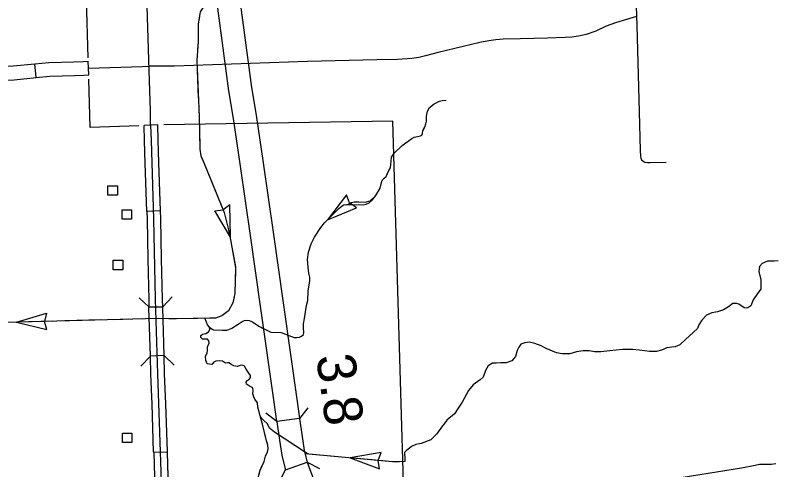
# Model space of a CAD drawing. Extents: x 155 to 3386, y 68 to 2138.
# Drawn here: x 1365.4 to 1602.6, y 911.3 to 1053.4 of the extents above; entities that cross this region are included whole.
import ezdxf

# ---------------------------------------------------------------- set-up
doc = ezdxf.new("R2010")
doc.units = 0
for name, color, linetype in [('Level 10', 7, 'Continuous'), ('Level 31', 7, 'Continuous'), ('Level 32', 7, 'Continuous'), ('Level 33', 7, 'Continuous'), ('Level 34', 7, 'Continuous'), ('Level 35', 7, 'Continuous'), ('Level 37', 7, 'Continuous'), ('Level 38', 7, 'Continuous'), ('Level 43', 7, 'Continuous'), ('Level 48', 7, 'Continuous'), ('Level 56', 7, 'Continuous'), ('Level 6', 7, 'Continuous')]:
    doc.layers.add(name, color=color, linetype=linetype)

msp = doc.modelspace()

# ---------------------------------------------------------------- linework, layer by layer
at = {"layer": 'Level 10'}
for p, q in [((1454.12, 927.28), (1447.04, 926.37)), ((1449.83, 911.26), (1456.56, 913.66))]:
    msp.add_line(p, q, dxfattribs=at)
for points in [[(1435.56, 1058.02), (1436.15, 1053.35), (1439.21, 1030.75), (1440.63, 1022.15), (1442.82, 1007.23), (1445.93, 985.55), (1449.17, 962.7), (1453.34, 933.37), (1454.12, 927.28)], [(1447.04, 926.37), (1446.26, 932.41), (1442.1, 961.7), (1438.86, 984.54), (1435.75, 1006.2), (1433.57, 1021.05), (1432.14, 1029.69), (1429.07, 1052.42), (1428.47, 1057.12)], [(1447.04, 926.37), (1447.06, 926.21), (1447.91, 920.57), (1448.64, 915.88), (1449.56, 912.02), (1449.83, 911.26)], [(1454.12, 927.28), (1454.13, 927.2), (1454.97, 921.66), (1455.66, 917.26), (1456.42, 914.06), (1456.56, 913.66)], [(1456.56, 913.66), (1457.39, 911.35), (1458.43, 908.69), (1459.74, 906.21), (1461.44, 903.5), (1463.17, 901.07), (1465.56, 898.29), (1467.5, 896.43), (1469.83, 894.48), (1472.23, 892.84), (1475.97, 890.67), (1486.91, 884.81)]]:
    msp.add_lwpolyline(points, dxfattribs=at)
at = {"layer": 'Level 31'}
for p, q in [((1410.78, 992.2), (1406.5, 992.05)), ((1410.78, 992.2), (1410.78, 992.2)), ((1407.21, 962.16), (1411.49, 962.24)), ((1411.89, 946.95), (1407.61, 946.82)), ((1412.91, 916.8), (1408.63, 916.66))]:
    msp.add_line(p, q, dxfattribs=at)
for points in [[(1410.28, 1007.27), (1410.05, 1014.28), (1409.9, 1019.04), (1405.62, 1018.9)], [(1406, 1007.13), (1405.77, 1014.14), (1405.62, 1018.9)], [(1420.96, 585), (1420.5, 602.36), (1419.65, 626.77), (1419.02, 651.18), (1418.35, 675.21), (1417.43, 699.69), (1416.62, 724.28), (1415.88, 748.76), (1415.17, 772.25), (1414.5, 794.97), (1413.66, 819.52), (1412.85, 843.76), (1412.35, 867.99), (1411.58, 891.84), (1410.77, 916.92), (1409.92, 941.23), (1409.21, 964.58), (1408.72, 989.66), (1407.91, 1014.21), (1407.76, 1018.97)], [(1406.5, 992.05), (1406, 1007.13)], [(1410.78, 992.2), (1410.28, 1007.27)], [(1406.5, 992.05), (1406.58, 989.61), (1406.83, 977)], [(1411.11, 977.09), (1410.86, 989.72), (1410.78, 992.2)], [(1406.83, 977), (1407.07, 964.53), (1407.15, 961.9)], [(1411.44, 962.03), (1411.36, 964.63), (1411.11, 977.09)], [(1407.61, 946.82), (1407.15, 961.9)], [(1411.89, 946.95), (1411.44, 962.03)], [(1408.11, 931.73), (1407.78, 941.16), (1407.61, 946.82)], [(1412.39, 931.88), (1412.06, 941.3), (1411.89, 946.95)], [(1408.63, 916.66), (1408.62, 916.85), (1408.11, 931.73)], [(1412.91, 916.8), (1412.91, 916.99), (1412.39, 931.88)], [(1408.63, 916.66), (1409.12, 901.58)], [(1413.4, 901.72), (1412.91, 916.8)]]:
    msp.add_lwpolyline(points, dxfattribs=at)
at = {"layer": 'Level 32'}
msp.add_line((1371.94, 1033.86), (1371.53, 1038.13), dxfattribs=at)
for points in [[(1356.6, 1037.18), (1364.8, 1037.48), (1371.53, 1038.13)], [(1371.53, 1038.13), (1375.88, 1038.55), (1383.72, 1038.83), (1386.72, 1038.92)], [(1386.72, 1038.92), (1388.21, 1038.97)], [(1386.86, 1034.64), (1388.35, 1034.68), (1388.21, 1038.97)], [(1371.94, 1033.86), (1376.16, 1034.27), (1383.86, 1034.54), (1386.86, 1034.64)], [(1356.76, 1032.9), (1365.08, 1033.2), (1371.94, 1033.86)]]:
    msp.add_lwpolyline(points, dxfattribs=at)
at = {"layer": 'Level 33'}
for points in [[(1564.93, 1075.72), (1560.18, 1074.28), (1559.67, 1073.92), (1559.16, 1073.37), (1558.88, 1072.82), (1558.8, 1072.11), (1558.8, 1071.16), (1559.51, 1050.17), (1560.22, 1023.19), (1560.5, 1011.04), (1560.62, 1009.27), (1560.73, 1008.72), (1561.01, 1008.2), (1561.44, 1007.77), (1562.04, 1007.45), (1562.82, 1007.3), (1563.65, 1007.3), (1568.66, 1007.42)], [(1407.66, 1018.97), (1407.61, 1023.44), (1407.2, 1036.12), (1406.36, 1062.97)], [(1559.42, 1052.99), (1556.25, 1052.01), (1552.82, 1050.94), (1549.91, 1049.88), (1546.67, 1048.38), (1543.72, 1047.31), (1541.31, 1046.8), (1539.22, 1046.49), (1537.17, 1046.37), (1531.61, 1046.17), (1523.06, 1045.93), (1517.77, 1045.82), (1515.53, 1045.62), (1513.32, 1045.38), (1510.52, 1044.83), (1497.51, 1041.67), (1493.49, 1040.61), (1491.48, 1040.18), (1489.23, 1039.86), (1484.81, 1039.5), (1478.29, 1039.43), (1456.65, 1038.91), (1415.13, 1037.45), (1407.16, 1037.44)]]:
    msp.add_lwpolyline(points, dxfattribs=at)
at = {"layer": 'Level 34'}
msp.add_lwpolyline([(1388.28, 1036.83), (1405.08, 1037.35), (1407.16, 1037.44)], dxfattribs=at)
at = {"layer": 'Level 35'}
for points in [[(1493.29, 1018.35), (1493.65, 1019.43), (1493.81, 1020.24), (1493.81, 1021.78), (1494.14, 1023.39), (1494.78, 1024.48), (1496.27, 1025.61), (1497.85, 1026.5), (1498.7, 1026.74), (1499.99, 1026.82)], [(1603.68, 976.54), (1602.36, 976.44), (1601.34, 976.44), (1600.27, 976.44), (1598.6, 975.73), (1597.78, 974.86), (1597.58, 973.29), (1598.19, 970.69), (1598.19, 969.37), (1598.19, 967.69), (1597.22, 966.32), (1595.8, 964.39), (1595.09, 962.49), (1594.22, 961.88), (1593.66, 961.83), (1593, 961.88), (1591.38, 963.05), (1590.67, 963.26), (1589.45, 963.2), (1588.12, 962.19), (1586.6, 961.27), (1584.72, 960.61), (1582.89, 960.36), (1581.26, 959.65), (1579.84, 958.07), (1578.88, 956.54), (1578.47, 955.42), (1577.15, 954.2), (1574.66, 951.97), (1572.93, 950.29), (1571.51, 949.73), (1570.44, 949.58), (1568.91, 949.42), (1567.24, 948.66), (1565.61, 948.26), (1564.44, 948.26), (1563.42, 948.26), (1560.32, 948.71), (1558.14, 948.87), (1555.04, 948.87), (1551.07, 948.46), (1548.22, 948.1), (1546.34, 948.1), (1544.66, 948.41), (1542.78, 948.41), (1540.65, 948.1), (1538.62, 947.54), (1536.18, 947.49), (1534.45, 947.8), (1531.2, 949.22), (1529.62, 950.03), (1527.64, 950.75), (1526.01, 951.15), (1524.49, 950.95), (1523.32, 950.49), (1522.71, 949.58), (1522.15, 948.51), (1521.64, 946.68), (1520.47, 945.31), (1518.74, 944.7), (1517.07, 944.7), (1515.7, 944.59), (1514.48, 944.59), (1513.05, 943.78), (1512.29, 942.26), (1511.53, 940.27), (1510.56, 939.41), (1508.38, 937.78), (1506.9, 936), (1504.97, 932.44), (1503.9, 930.81), (1502.53, 928.73), (1500.19, 926.8), (1499.08, 925.22), (1498.82, 925.02), (1496.94, 922.42), (1495.21, 920.64), (1492.21, 919.47), (1490.54, 919.22), (1489.11, 918.56), (1487.49, 917.24)], [(1441.11, 930.84), (1441.06, 932.16), (1440.19, 933.39), (1439.89, 934.1), (1439.64, 934.96), (1439.74, 935.93), (1439.59, 936.89), (1438.52, 937.45), (1437.6, 938.06), (1437.5, 938.67), (1437.81, 939.13), (1438.47, 939.44), (1438.87, 940.15), (1438.82, 940.76), (1438.37, 941.47), (1437.5, 942.69), (1437.04, 943.66), (1436.59, 943.91), (1435.98, 943.96), (1434.66, 943.55), (1433.69, 943.71), (1432.83, 944.22), (1432.16, 944.72), (1431.71, 944.67), (1431.05, 944.62), (1430.13, 945.18), (1429.32, 945.28), (1428, 945.23), (1427.44, 944.88), (1426.83, 944.17), (1425.35, 944.37), (1424.95, 945.44), (1424.8, 946.71), (1425.35, 947.78), (1425.46, 948.44), (1425.46, 949.66), (1425.96, 950.83), (1425.86, 951.54), (1425.41, 952.05), (1424.59, 952.05), (1423.88, 952.05), (1423.37, 952.61), (1423.32, 953.22), (1423.88, 953.67), (1424.95, 953.88), (1425.76, 954.44), (1426.12, 955.1), (1426.07, 955.81), (1425.41, 956.57), (1425.1, 957.39), (1424.64, 958.64)]]:
    msp.add_lwpolyline(points, dxfattribs=at)
at = {"layer": 'Level 37'}
for points in [[(1456.74, 930.67), (1454.12, 927.28)], [(1447.04, 926.37), (1443.64, 928.98)], [(1456.58, 913.61), (1460.42, 911.72)], [(1447.93, 907.46), (1449.82, 911.31)]]:
    msp.add_lwpolyline(points, dxfattribs=at)
at = {"layer": 'Level 38'}
for points in [[(1407.21, 962.11), (1404.09, 965.05)], [(1414.43, 965.36), (1411.49, 962.24)], [(1404.67, 943.7), (1407.61, 946.82)], [(1411.89, 946.95), (1415.01, 944.01)]]:
    msp.add_lwpolyline(points, dxfattribs=at)
at = {"layer": 'Level 43'}
for p, q in [((1468.83, 997.17), (1462.86, 989.39)), ((1469.83, 994.75), (1468.83, 997.17)), ((1432.42, 994.12), (1430.34, 992.54)), ((1432.57, 984.03), (1432.42, 994.12)), ((1471.92, 993.14), (1469.85, 994.73)), ((1427.72, 992.19), (1430.31, 992.52)), ((1432.57, 984.03), (1427.72, 992.19)), ((1462.86, 989.39), (1471.92, 993.14)), ((1365.77, 957.4), (1375.18, 960.18)), ((1375.18, 960.18), (1374.57, 957.64)), ((1365.77, 957.4), (1375.31, 955.11)), ((1375.31, 955.11), (1374.57, 957.61)), ((1479.62, 916.63), (1469.95, 914.97)), ((1478.71, 914.18), (1479.62, 916.63)), ((1469.95, 914.97), (1479.15, 911.57)), ((1479.15, 911.57), (1478.71, 914.14))]:
    msp.add_line(p, q, dxfattribs=at)
for points in [[(1427.81, 1062.03), (1425.1, 1057.42), (1423.16, 1054.38), (1422.92, 1053.17), (1422.55, 1050.62), (1422.55, 1045.15), (1422.07, 1039.2), (1422.8, 1021.66), (1423.04, 1011.46), (1423.4, 1009.39), (1424.37, 1006.96), (1430.69, 991.66), (1432.02, 986.25), (1432.75, 982.61), (1434.21, 974.35), (1433.96, 966.33), (1433.36, 963.42), (1432.02, 960.99), (1429.96, 959.41), (1427.89, 958.68), (1426.19, 958.68), (1415.75, 958.44), (1410.05, 958.56), (1354.51, 957.1)], [(1422.89, 1052.99), (1422.55, 1050.62), (1422.55, 1045.15), (1422.35, 1042.65)], [(1422.19, 1036.2), (1422.55, 1027.58)], [(1422.71, 1023.82), (1422.8, 1021.66), (1423.01, 1012.51)], [(1426.07, 955.81), (1426.45, 955.52), (1426.85, 955.2), (1427.33, 954.99), (1430.04, 954.91), (1431.33, 954.91), (1432.1, 955.07), (1433.06, 955.56), (1435.04, 956.81), (1436.25, 957.66), (1437.02, 957.94), (1437.71, 958.02), (1438.47, 957.9), (1439.48, 957.5), (1441.5, 956.12), (1445.21, 954.27), (1448.4, 954.19), (1451.67, 952.89), (1452.48, 952.61), (1453.28, 952.57), (1454.17, 952.69), (1454.82, 953.02), (1455.38, 953.54), (1455.5, 954.15), (1455.38, 955.6), (1455.38, 956.89), (1455.75, 958.55), (1456.15, 961.29), (1456.35, 962.59), (1456.76, 964.2), (1456.88, 967.23), (1457.36, 970.26), (1457.44, 971.44), (1457.08, 972.7), (1456.84, 974.55), (1456.71, 976.98), (1457, 979.24), (1457.76, 981.94), (1458.89, 983.96), (1460.79, 986.95), (1461.97, 988.49), (1466.41, 992.97), (1467.5, 993.82), (1468.06, 994.07), (1468.87, 994.23), (1470.32, 994.23), (1474.08, 994.11), (1475.01, 994.31), (1475.89, 994.75), (1476.82, 995.56), (1477.99, 996.97), (1479.32, 999.31), (1479.85, 1001.45), (1480.13, 1001.94), (1480.57, 1002.46), (1481.22, 1002.95), (1482.07, 1004.85), (1482.63, 1005.69), (1482.75, 1007.73), (1482.92, 1008.94), (1483.68, 1010.19), (1486.18, 1012.58), (1489.25, 1014.84), (1489.98, 1015.28), (1490.99, 1015.44), (1491.92, 1015.64), (1492.4, 1015.89), (1492.6, 1016.37), (1492.64, 1017.26), (1493.29, 1018.35)], [(1492.82, 1017.56), (1493.29, 1018.35)], [(1482.75, 1007.73), (1482.92, 1008.94), (1483.68, 1010.19), (1486.18, 1012.58), (1489.25, 1014.84), (1489.98, 1015.28), (1490.48, 1015.36)], [(1423.63, 1008.81), (1424.37, 1006.96), (1427.93, 998.34)], [(1479.31, 999.29), (1479.32, 999.31), (1479.85, 1001.45), (1480.13, 1001.94), (1480.57, 1002.46), (1481.22, 1002.95), (1481.78, 1004.19)], [(1474.66, 994.94), (1476.25, 995.3), (1477.99, 996.97), (1479.31, 999.29)], [(1429.37, 994.86), (1430.69, 991.66), (1432.02, 986.25), (1432.16, 985.58)], [(1469.48, 994.32), (1469.84, 994.6), (1470.41, 994.85), (1471.22, 995.01), (1472.67, 995.01), (1474.66, 994.94)], [(1456.76, 976.04), (1456.71, 976.98), (1457, 979.24), (1457.76, 981.94), (1458.89, 983.96), (1459.2, 984.44)], [(1433.16, 980.3), (1434.14, 974.73)], [(1434.14, 974.73), (1434.21, 974.35), (1434.05, 969.08)], [(1456.13, 961.13), (1456.15, 961.29), (1456.35, 962.59), (1456.76, 964.2), (1456.88, 967.23), (1457.36, 970.26), (1457.44, 971.44), (1457.19, 972.3)], [(1433.76, 965.34), (1433.36, 963.42), (1432.02, 960.99), (1429.96, 959.41), (1427.89, 958.68), (1426.19, 958.68), (1426.1, 958.68)], [(1405.03, 958.43), (1395.94, 958.19)], [(1422.33, 958.59), (1415.75, 958.44), (1413.41, 958.49)], [(1377.09, 957.69), (1365.77, 957.4)], [(1392.17, 958.09), (1380.86, 957.79)], [(1434.79, 956.65), (1435.04, 956.81), (1436.25, 957.66), (1437.02, 957.94), (1437.71, 958.02), (1438.47, 957.9), (1439.48, 957.5), (1441.5, 956.12), (1442.61, 955.57)], [(1450.86, 953.21), (1451.67, 952.89), (1452.48, 952.61), (1453.28, 952.57), (1454.17, 952.69), (1454.82, 953.02), (1455.38, 953.54), (1455.5, 954.15), (1455.38, 955.6), (1455.38, 956.89), (1455.5, 957.42)], [(1426.07, 955.81), (1426.45, 955.52), (1426.85, 955.2), (1427.33, 954.99), (1430.04, 954.91), (1431.33, 954.91), (1431.47, 954.94)], [(1439.89, 902.7), (1440.35, 905.27), (1441.87, 911.16), (1443.09, 913.86), (1443.6, 915.49), (1444.21, 916.91), (1444.36, 917.83), (1444.26, 918.94), (1443.85, 920.32), (1442.58, 925.55), (1441.92, 928.1), (1441.11, 930.84)], [(1442.4, 926.26), (1441.92, 928.1), (1441.11, 930.84)], [(1487.49, 917.24), (1486.98, 916.68), (1487.03, 914.69), (1487.03, 913.83), (1485.35, 913.73), (1483.22, 913.73), (1457.1, 916.17), (1455.77, 916.88), (1446.32, 922.98), (1444.75, 924.31), (1444.14, 925.63), (1442.92, 926.8), (1441.99, 927.84)], [(1442.17, 911.83), (1443.09, 913.86), (1443.6, 915.49), (1444.21, 916.91), (1444.36, 917.83), (1444.26, 918.94), (1443.85, 920.32), (1443.3, 922.6)], [(1466.2, 915.32), (1455.81, 916.29)], [(1487.49, 917.24), (1486.98, 916.68), (1487.03, 914.69), (1487.03, 913.83), (1485.35, 913.73), (1484.98, 913.73)], [(1481.22, 913.92), (1469.95, 914.97)], [(1602.88, 913.1), (1601.51, 912.94), (1599.63, 912.94), (1597.85, 912.89), (1596.43, 912.64), (1592.16, 911.77), (1563.59, 907.2)], [(1600.75, 912.94), (1599.63, 912.94), (1597.85, 912.89), (1596.43, 912.64), (1592.16, 911.77), (1589.58, 911.36)]]:
    msp.add_lwpolyline(points, dxfattribs=at)
at = {"layer": 'Level 56'}
for points in [[(1394.29, 997.08), (1394.29, 1000.05), (1397.28, 1000.05), (1397.28, 997.08)], [(1398.75, 989.56), (1398.75, 992.53), (1401.73, 992.53), (1401.73, 989.56)], [(1396.02, 973.79), (1396.02, 976.76), (1399, 976.76), (1399, 973.79)], [(1398.85, 919.78), (1398.85, 922.75), (1401.83, 922.75), (1401.83, 919.78)]]:
    msp.add_lwpolyline(points, close=True, dxfattribs=at)
at = {"layer": 'Level 6'}
for points in [[(1388.19, 1039.98), (1386.09, 1113.47), (1325.89, 1111.06), (1324.11, 1178.97), (1314.71, 1177.54), (1314.46, 1187.22), (1314.07, 1201.9)], [(1403.99, 1018.82), (1388.82, 1018.22), (1388.38, 1033.33)], [(1487.24, 886.06), (1483.35, 1020.26), (1411.81, 1019.04)]]:
    msp.add_lwpolyline(points, dxfattribs=at)

# ---------------------------------------------------------------- texts
at = {"layer": 'Level 48'}
msp.add_text('3.8', height=12.069, rotation=278.0017, dxfattribs=at).set_placement((1459.32, 946.72))

doc.saveas('drawing.dxf')
